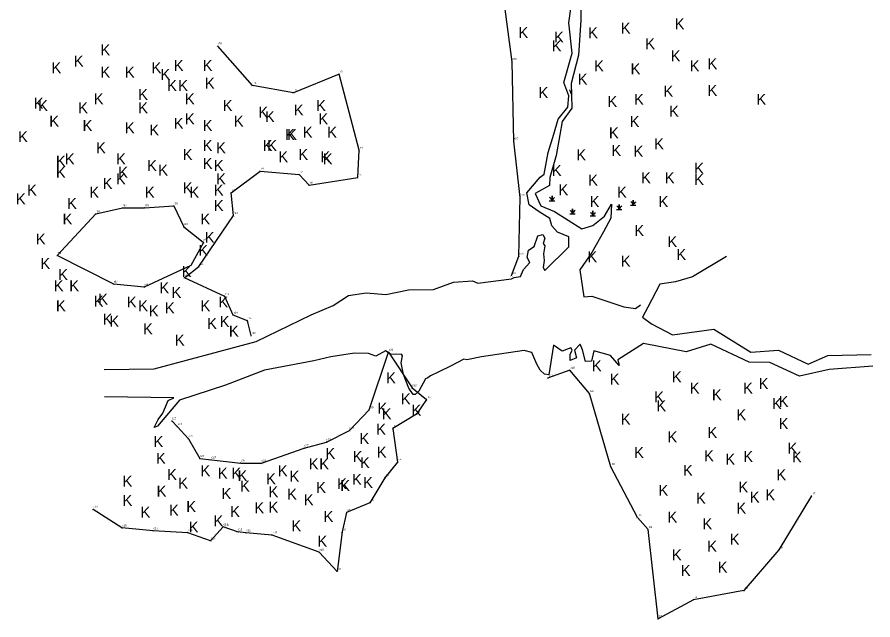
# Model space of a CAD drawing. Extents: x 2028512 to 2029541, y 737100 to 738747.
# Drawn here: x 2028512 to 2029176, y 737100 to 737568 of the extents above; entities that cross this region are included whole.
import ezdxf

# ---------------------------------------------------------------- set-up
doc = ezdxf.new("R2010")
doc.units = 0
for name, color, linetype in [('Exist Hydro Jurisdictional Stream or Body of Water NEU Mitigable', 7, 'Continuous'), ('Exist Hydro Jurisdictional Stream or Body of Water NEU NonMitigable', 7, 'Continuous'), ('Exist Hydro Swamp or Marsh', 7, 'Continuous'), ('Old_Level_10', 7, 'Continuous'), ('Old_Level_20', 7, 'Continuous'), ('Old_Level_52', 7, 'Continuous'), ('Old_Level_55', 7, 'Continuous'), ('Old_Level_61', 7, 'Continuous')]:
    doc.layers.add(name, color=color, linetype=linetype)

msp = doc.modelspace()

# ---------------------------------------------------------------- linework, layer by layer
at = {"layer": 'Exist Hydro Jurisdictional Stream or Body of Water NEU Mitigable'}
for points in [[(2028936, 737517.23), (2028942.42, 737539.85), (2028939.91, 737563.38), (2028944.05, 737593.1), (2028942.37, 737627.04), (2028952.81, 737663.43), (2028963.03, 737695.43), (2028966.79, 737709.62), (2028967.55, 737730.9), (2028965.32, 737734.83), (2028966.1, 737772.62), (2028976.38, 737791.55), (2028994.69, 737794.94), (2029012.11, 737812.51), (2029020.64, 737839.95), (2029044.47, 737843.01), (2029064.89, 737861), (2029074.27, 737865.65)], [(2029086.17, 737861.26), (2029065.82, 737853.05), (2029047.81, 737826.9), (2029032.96, 737828.41), (2029014.3, 737805.56), (2029001.47, 737787.92), (2029013.48, 737774.19), (2029008.57, 737742.32), (2028993.96, 737712.46), (2028973.16, 737694.62), (2028970.92, 737694.24), (2028956.66, 737656.32), (2028948.19, 737625.98), (2028949.49, 737593.57), (2028949.29, 737565.55), (2028947.28, 737538.25), (2028941.59, 737516.37), (2028941.83, 737507.52)], [(2028579.28, 737294.49), (2028618.11, 737294.82), (2028668.37, 737308.4), (2028697.25, 737316.02), (2028739.8, 737336.89), (2028756.85, 737344.17), (2028768.94, 737351.84), (2028782.65, 737353.85), (2028797.96, 737352.7), (2028815.53, 737356.13), (2028834.91, 737356.47), (2028850.48, 737362.29), (2028865.05, 737363.12), (2028869.24, 737361.53), (2028895.29, 737364.79), (2028897.35, 737365.88), (2028902.23, 737366.59), (2028904.64, 737371.95), (2028909.52, 737377.53), (2028907.4, 737381.33), (2028908.6, 737387.08), (2028912.94, 737389.99), (2028915.87, 737398.06), (2028919.61, 737399.24), (2028921.19, 737396.31), (2028919.98, 737392.28), (2028921.28, 737390.26), (2028920.09, 737384.28), (2028920.77, 737379.09), (2028919.88, 737373.45), (2028921.21, 737371.27), (2028939.9, 737389.63), (2028939.73, 737397.45), (2028931.07, 737401.07), (2028926.71, 737405.79), (2028925.13, 737411.52), (2028916.94, 737416.7), (2028909.17, 737422.08), (2028907.26, 737431.54), (2028917.65, 737443.63), (2028920.61, 737446.09), (2028923.86, 737462.71), (2028928.34, 737476.94), (2028931.47, 737488.65), (2028939.13, 737497.99), (2028939.73, 737506.91), (2028936, 737517.23)], [(2028956.69, 737515.78), (2028956.69, 737515.78), (2028956.69, 737515.78)], [(2028940.27, 737511.64), (2028941.83, 737507.52), (2028942.13, 737497.36), (2028934.67, 737486.92), (2028932.85, 737476.66), (2028929.99, 737460.54), (2028925.08, 737443.5), (2028924.85, 737437.17), (2028913.73, 737430.92), (2028918.01, 737421.53), (2028928.81, 737417.07), (2028949.92, 737403.52), (2028958.51, 737406.06), (2028967.65, 737413.3), (2028972.86, 737422.71), (2028972.54, 737411.9), (2028966.68, 737401.35)], [(2028966.68, 737401.35), (2028957.77, 737385.32), (2028948.3, 737371.74), (2028951.59, 737350.67), (2028951.59, 737350.67), (2028957.63, 737351.39), (2028982.64, 737343.14), (2028991.65, 737341.83), (2028995.35, 737344.57)], [(2028997.07, 737335.1), (2029004.09, 737329.88), (2029020.36, 737321.25), (2029052.42, 737325.7), (2029080.99, 737307.79), (2029102.51, 737309.37), (2029125.49, 737298.64), (2029140.85, 737305.29), (2029174.35, 737306.1)], [(2029175.81, 737296.95), (2029141.96, 737294.49), (2029118.74, 737289.3), (2029095.9, 737299.77), (2029079.76, 737299.97), (2029050.15, 737314), (2029030.96, 737308.01), (2028997.7, 737314.69), (2028977.92, 737301.97), (2028978.95, 737297.5), (2028972.13, 737305.22), (2028959.18, 737308.95), (2028957.35, 737300.91), (2028952.91, 737300.7), (2028950.53, 737309.54), (2028948.58, 737314.03), (2028944.32, 737309.45), (2028945.88, 737303.52), (2028940.97, 737301.5), (2028940.99, 737305.95), (2028942.42, 737309.49), (2028941.29, 737311.1), (2028934.72, 737308.65), (2028928, 737313.22), (2028924.46, 737290.33), (2028920.89, 737290.83), (2028917.54, 737293.89), (2028914.92, 737298.41), (2028911.07, 737307.65), (2028905.11, 737309.14), (2028871.99, 737304.25), (2028860.77, 737301.82), (2028858.36, 737302.4), (2028847.98, 737296.86), (2028839.03, 737292.52), (2028832.58, 737289.46), (2028830.34, 737287.86), (2028828.6, 737287.08), (2028823.58, 737277.67), (2028820.68, 737275.02), (2028819.16, 737274.91), (2028815.73, 737279.86), (2028811.67, 737290.39), (2028809.82, 737299.53), (2028810.76, 737305.1), (2028810.06, 737306.41), (2028801.97, 737306.06), (2028797.58, 737308.87), (2028790.08, 737304.86), (2028784.27, 737306.84), (2028773.47, 737307.03), (2028755.08, 737304.25), (2028741.96, 737301.19), (2028703.61, 737293.82), (2028703.61, 737293.82), (2028673.41, 737282.3), (2028637.63, 737270.65), (2028620.59, 737250.44), (2028618.02, 737249.4), (2028621.23, 737255.67), (2028624.74, 737260.61), (2028628.88, 737270.21), (2028633.29, 737272.32), (2028579.58, 737273.18)]]:
    msp.add_lwpolyline(points, dxfattribs=at)
at = {"layer": 'Exist Hydro Jurisdictional Stream or Body of Water NEU NonMitigable'}
msp.add_lwpolyline([(2029062.34, 737382.21), (2029035.93, 737366.44), (2029022.72, 737362.46), (2029010.52, 737360.74), (2029001.14, 737342.82), (2028997.07, 737335.1)], dxfattribs=at)
at = {"layer": 'Exist Hydro Swamp or Marsh'}
for p, q in [((2028926.82, 737427.1), (2028926.82, 737427.1)), ((2028978.92, 737420.34), (2028978.92, 737420.34)), ((2028989.77, 737423.61), (2028989.77, 737423.61)), ((2028942.69, 737416.96), (2028942.69, 737416.96)), ((2028958.45, 737415.32), (2028958.45, 737415.32))]:
    msp.add_line(p, q, dxfattribs=at)
for points in [[(2028924.67, 737425.31), (2028926.83, 737425.31), (2028926.83, 737429.26), (2028926.83, 737425.31), (2028928.98, 737425.31)], [(2028976.77, 737418.55), (2028978.93, 737418.55), (2028978.93, 737422.5), (2028978.93, 737418.55), (2028981.08, 737418.55)], [(2028987.62, 737421.83), (2028989.78, 737421.83), (2028989.78, 737425.78), (2028989.78, 737421.83), (2028991.93, 737421.83)], [(2028940.54, 737415.17), (2028942.69, 737415.17), (2028942.69, 737419.12), (2028942.69, 737415.17), (2028944.84, 737415.17)], [(2028956.3, 737413.54), (2028958.45, 737413.54), (2028958.45, 737417.48), (2028958.45, 737413.54), (2028960.6, 737413.54)]]:
    msp.add_lwpolyline(points, dxfattribs=at)
for centre, radius, start, end in [((2028923.76, 737425.09), 3.07, 4.14034, 67.53497), ((2028931.39, 737423.8), 4.81, 122.12745, 161.62219), ((2028975.86, 737418.33), 3.07, 4.14034, 67.53497), ((2028983.49, 737417.04), 4.81, 122.12745, 161.62219), ((2028986.71, 737421.61), 3.07, 4.14034, 67.53497), ((2028994.34, 737420.32), 4.81, 122.12745, 161.62219), ((2028939.62, 737414.95), 3.07, 4.14034, 67.53497), ((2028947.25, 737413.66), 4.81, 122.12745, 161.62219), ((2028955.39, 737413.31), 3.07, 4.14034, 67.53497), ((2028963.01, 737412.02), 4.81, 122.12745, 161.62219)]:
    msp.add_arc(centre, radius, start, end, dxfattribs=at)
at = {"layer": 'Old_Level_52'}
for points in [[(2028895.42, 737367.29), (2028901.12, 737382.42), (2028902.03, 737427.96), (2028897.22, 737471.61), (2028895.79, 737533.3), (2028886.82, 737601.44), (2028880.64, 737719.02)], [(2028694.5, 737514.77), (2028667.38, 737545.48)], [(2028693.4, 737320.71), (2028690.55, 737332.26), (2028679.49, 737336.57), (2028672.9, 737351.1), (2028641.49, 737365.44), (2028652.64, 737374.31), (2028679.69, 737413.85), (2028677.78, 737431.5), (2028700.22, 737448.42), (2028730.65, 737445.78), (2028738.36, 737437.46), (2028776.16, 737443.51), (2028777.17, 737464.61), (2028761.51, 737523.75), (2028726.26, 737509.21), (2028694.5, 737514.77)], [(2028646.52, 737375.03), (2028610.39, 737358.35), (2028586.64, 737360.64), (2028542.87, 737382.85), (2028572.83, 737415.22), (2028593.56, 737419.88), (2028610.55, 737419.9), (2028633.35, 737421.42), (2028641.02, 737405.22), (2028656.21, 737393.15), (2028656.33, 737393.09), (2028646.52, 737375.03)], [(2028631.79, 737254.52), (2028636.15, 737250), (2028644.82, 737240.66), (2028653.53, 737225.35), (2028662.6, 737224.3), (2028685.23, 737221.76), (2028701.36, 737221.65), (2028734.42, 737233.45), (2028751.76, 737238.1), (2028769.64, 737247.12), (2028784.82, 737262.97), (2028799.89, 737307.85), (2028818.26, 737280.17), (2028829.48, 737271.13), (2028821.53, 737259.75), (2028803.29, 737248.65), (2028807, 737222.55), (2028797.08, 737210.34), (2028785.33, 737191.01), (2028767.41, 737183.39), (2028763.87, 737168.27), (2028759.99, 737137.67), (2028746.04, 737152.6), (2028709.71, 737165.9), (2028689.31, 737167.63), (2028682.75, 737168.31), (2028671.67, 737172.24), (2028661.89, 737161.44), (2028644.29, 737167.68), (2028617.36, 737169.18), (2028593.06, 737171.4), (2028570.75, 737185.76), (2028570.79, 737185.85)]]:
    msp.add_lwpolyline(points, dxfattribs=at)
at = {"layer": 'Old_Level_55'}
msp.add_lwpolyline([(2029128.06, 737196.31), (2029102.78, 737154.4), (2029075.75, 737122.77), (2029036.51, 737115.67), (2029009.19, 737100.79), (2029001.45, 737170.2), (2028993.06, 737179.45), (2028972.4, 737218.95), (2028955.96, 737275.67), (2028940.73, 737293.83), (2028923.43, 737287.61)], dxfattribs=at)

# ---------------------------------------------------------------- texts
at = {"layer": 'Old_Level_10'}
for p in [(2029022, 737558.4), (2028900.79, 737551.66), (2028954.83, 737551.56), (2028980.17, 737555.11), (2028928.4, 737548.21), (2028576.36, 737538.19), (2028926.67, 737541.3), (2028999.15, 737543.03), (2029018.89, 737533.53), (2028538.39, 737524.38), (2028555.65, 737529.56), (2028616.05, 737524.38), (2028633.3, 737526.11), (2028655.74, 737526.11), (2028959.46, 737525.76), (2029033.67, 737525.76), (2029047.47, 737527.49), (2028576.36, 737520.93), (2028595.34, 737520.93), (2028622.95, 737519.2), (2028987.8, 737523.57), (2028657.46, 737512.3), (2028946.75, 737515.49), (2028628.13, 737510.57), (2028636.76, 737510.57), (2028916.32, 737505.04), (2029013.3, 737506.16), (2029047.47, 737506.77), (2028571.18, 737500.21), (2028605.69, 737503.66), (2028641.93, 737500.21), (2028969.82, 737498.14), (2028990.52, 737499.86), (2029085.44, 737499.86), (2028524.59, 737496.76), (2028528.04, 737495.03), (2028559.1, 737493.3), (2028605.69, 737493.3), (2028671.27, 737495.03), (2028726.49, 737491.58), (2028743.75, 737495.03), (2028641.93, 737484.67), (2028698.88, 737489.85), (2028704.06, 737486.4), (2028745.48, 737484.67), (2029017.65, 737490.61), (2028536.67, 737482.94), (2028562.55, 737479.49), (2028595.34, 737477.76), (2028633.3, 737481.22), (2028655.74, 737479.49), (2028679.9, 737482.94), (2028987.07, 737482.6), (2028614.32, 737476.04), (2028719.59, 737472.58), (2028721.32, 737472.58), (2028733.4, 737474.31), (2028752.38, 737474.31), (2028971, 737473.82), (2028971, 737473.82), (2028512.51, 737470.86), (2029006.05, 737465.33), (2028572.91, 737462.22), (2028655.74, 737463.95), (2028666.09, 737462.22), (2028702.33, 737463.95), (2028705.78, 737463.95), (2028972.87, 737460.14), (2028990.05, 737459.52), (2028541.84, 737451.86), (2028548.75, 737453.59), (2028588.44, 737453.59), (2028640.21, 737457.04), (2028714.41, 737455.32), (2028729.94, 737457.04), (2028747.2, 737455.32), (2028748.93, 737453.59), (2028945.66, 737456.7), (2028612.6, 737448.41), (2028621.23, 737444.96), (2028655.74, 737450.14), (2028664.37, 737448.41), (2028926.67, 737444.61), (2029037.12, 737446.34), (2028541.84, 737443.23), (2028588.44, 737438.05), (2028590.16, 737443.23), (2028666.09, 737438.05), (2028995.88, 737438.99), (2029014.3, 737438.99), (2029037.12, 737437.71), (2028578.08, 737434.6), (2028640.21, 737431.14), (2028954.83, 737437.13), (2028519.41, 737429.42), (2028567.73, 737427.69), (2028610.87, 737427.69), (2028645.39, 737427.69), (2028664.37, 737429.42), (2028931.82, 737429.66), (2028977.22, 737427.8), (2028510.78, 737422.51), (2028550.47, 737419.06), (2028956.01, 737420.44), (2029009.51, 737420.44), (2028664.37, 737417.33), (2028547.02, 737406.97), (2028654.01, 737406.97), (2028990.67, 737397.94), (2028526.31, 737391.43), (2028657.4, 737392.73), (2029016.41, 737389.36), (2028652.36, 737382.64), (2029023.31, 737379.35), (2028529.76, 737372.44), (2028954.28, 737377.62), (2028980.17, 737374.17), (2028639.4, 737366.31), (2028543.57, 737363.81), (2028540.12, 737355.17), (2028552.2, 737355.17), (2028622.12, 737353.59), (2028574.63, 737344.81), (2028631.58, 737349.99), (2028541.84, 737339.64), (2028571.18, 737343.09), (2028596.92, 737342.54), (2028605.69, 737339.64), (2028654.01, 737339.64), (2028667.96, 737342.54), (2028613.96, 737335.58), (2028626.4, 737337.91), (2028578.08, 737329.28), (2028583.26, 737327.55), (2028659.19, 737325.82), (2028668.92, 737327.42), (2028609.4, 737321.66), (2028676.11, 737319.97), (2028634.12, 737313.01), (2028957.74, 737293.02), (2028798.02, 737283.62), (2028971.54, 737282.66), (2029019.86, 737284.38), (2029087.16, 737279.2), (2029033.67, 737275.75), (2029075.08, 737275.75), (2028809.54, 737267.3), (2029006.05, 737268.84), (2029050.92, 737270.57), (2029102.69, 737265.39), (2028791.3, 737260.09), (2028817.7, 737258.65), (2029007.78, 737261.94), (2029097.52, 737263.66), (2028794.66, 737255.77), (2029069.91, 737255.03), (2028980.17, 737251.58), (2029102.69, 737248.13), (2028790.34, 737243.77), (2029047.47, 737241.22), (2028617.56, 737234.16), (2028777.38, 737236.56), (2029016.41, 737237.77), (2028790.82, 737226), (2028990.52, 737225.68), (2029109.6, 737229.13), (2028619.48, 737221.2), (2028750.99, 737225.04), (2028772.1, 737222.64), (2029044.78, 737223.18), (2029061.28, 737220.5), (2029075.25, 737222.56), (2029113.05, 737222.23), (2028738.03, 737216.87), (2028746.19, 737216.87), (2028777.86, 737217.83), (2028628.12, 737208.71), (2028654.04, 737211.59), (2028667.48, 737209.67), (2028678.03, 737209.67), (2028682.83, 737207.75), (2028704.91, 737205.35), (2028714.03, 737211.59), (2028723.15, 737207.27), (2029028.49, 737211.87), (2029100.97, 737208.41), (2028593.56, 737203.43), (2028636.76, 737201.99), (2028684.75, 737199.59), (2028743.79, 737198.63), (2028760.11, 737201.51), (2028762.51, 737200.07), (2028771.63, 737204.87), (2028780.26, 737202.47), (2029071.52, 737198.93), (2028619.96, 737195.75), (2028670.36, 737193.82), (2028706.83, 737195.27), (2028721.23, 737193.34), (2029009.51, 737196.33), (2029092.34, 737192.87), (2028593.56, 737188.54), (2028734.19, 737189.02), (2029038.56, 737190.22), (2029080.26, 737191.15), (2028607.48, 737179.42), (2028629.56, 737180.86), (2028643, 737183.74), (2028677.07, 737179.9), (2028695.79, 737182.78), (2028706.83, 737183.26), (2029069.91, 737182.51), (2028664.12, 737172.7), (2028749.55, 737176.06), (2029016.41, 737175.61), (2028644.92, 737167.89), (2028724.59, 737168.85), (2029043.53, 737170.32), (2028744.75, 737156.85), (2029047.26, 737152.9), (2029064.73, 737158.34), (2029019.86, 737146.26), (2029026.76, 737134.17), (2029055.35, 737136.73)]:
    msp.add_text('K', height=8.5, dxfattribs=at).set_placement(p)
at = {"layer": 'Old_Level_20'}
for p in [(2028666.63, 737544.73), (2028895.04, 737532.55), (2028760.76, 737523), (2028693.75, 737514.02), (2028725.51, 737508.46), (2028896.47, 737470.86), (2028776.42, 737463.86), (2028699.47, 737447.67), (2028729.9, 737445.03), (2028775.41, 737442.76), (2028737.61, 737436.71), (2028677.03, 737430.75), (2028901.28, 737427.21), (2028592.81, 737419.13), (2028609.8, 737419.15), (2028632.6, 737420.67), (2028572.08, 737414.47), (2028678.94, 737413.1), (2028640.27, 737404.47), (2028655.58, 737392.34), (2028542.12, 737382.1), (2028900.37, 737381.67), (2028651.89, 737373.56), (2028894.67, 737366.54), (2028585.89, 737359.89), (2028640.74, 737364.69), (2028609.64, 737357.6), (2028672.15, 737350.35), (2028678.74, 737335.82), (2028689.8, 737331.51), (2028692.65, 737319.96), (2028799.14, 737307.1), (2028939.98, 737293.08), (2028922.68, 737286.86), (2028817.51, 737279.42), (2028955.21, 737274.92), (2028828.73, 737270.38), (2028784.07, 737262.22), (2028820.78, 737259), (2028631.04, 737253.77), (2028635.4, 737249.25), (2028768.89, 737246.37), (2028802.54, 737247.9), (2028644.07, 737239.91), (2028733.67, 737232.7), (2028751.01, 737237.35), (2028652.78, 737224.6), (2028661.85, 737223.55), (2028684.48, 737221.01), (2028700.61, 737220.9), (2028806.25, 737221.8), (2028971.65, 737218.2), (2028796.33, 737209.59), (2029127.31, 737195.56), (2028784.58, 737190.26), (2028570.04, 737185.1), (2028766.66, 737182.64), (2028992.31, 737178.7), (2028592.31, 737170.65), (2028616.61, 737168.43), (2028643.54, 737166.93), (2028670.92, 737171.49), (2028672.54, 737171.01), (2028682, 737167.56), (2028688.56, 737166.88), (2028763.12, 737167.52), (2029000.7, 737169.45), (2028661.14, 737160.69), (2028708.96, 737165.15), (2029102.03, 737153.65), (2028745.29, 737151.85), (2028759.24, 737136.92), (2029075, 737122.02), (2029035.76, 737114.92), (2029008.44, 737100.04)]:
    msp.add_text('A', height=1.5, dxfattribs=at).set_placement(p)
at = {"layer": 'Old_Level_61'}
for s, p in [('r70', (2028667.49, 737546.73)), ('a78', (2028895.84, 737534.55)), ('r3', (2028762.36, 737525)), ('r1', (2028695.6, 737516.02)), ('r2', (2028727.11, 737510.46)), ('a77', (2028897.26, 737472.86)), ('r4', (2028778.02, 737465.86)), ('r8', (2028701.07, 737449.67)), ('r7', (2028731.5, 737447.03)), ('r5', (2028777.01, 737444.76)), ('r6', (2028739.21, 737438.71)), ('r9', (2028678.62, 737432.75)), ('a76', (2028902.08, 737429.21)), ('r90', (2028593.68, 737421.13)), ('r91', (2028610.92, 737421.15)), ('r92', (2028633.47, 737422.67)), ('r99', (2028572.95, 737416.47)), ('r10', (2028680.05, 737415.1)), ('r93', (2028641.13, 737406.47)), ('r94', (2028656.45, 737394.34)), ('r98', (2028542.98, 737384.1)), ('a75', (2028901.17, 737383.67)), ('r11', (2028653.26, 737375.56)), ('r12', (2028641.85, 737366.69)), ('a74', (2028895.47, 737368.54)), ('r97', (2028586.75, 737361.89)), ('r96', (2028610.5, 737359.6)), ('r13', (2028673.26, 737352.35)), ('r14', (2028679.86, 737337.82)), ('r15', (2028690.92, 737333.51)), ('r16', (2028693.76, 737321.96)), ('c31', (2028800.22, 737309.1)), ('b10', (2028941.02, 737295.08)), ('b11', (2028923.97, 737288.86)), ('c32', (2028818.33, 737281.42)), ('c1', (2028830.51, 737272.38)), ('b9', (2028956.73, 737276.92)), ('c30', (2028784.89, 737264.22)), ('c2', (2028822.31, 737261)), ('c20', (2028631.83, 737255.77)), ('c21', (2028636.45, 737251.25)), ('c29', (2028769.68, 737248.37)), ('c3', (2028804.06, 737249.9)), ('c22', (2028644.87, 737241.91)), ('c28', (2028751.81, 737239.35)), ('c27', (2028734.46, 737234.7)), ('c23', (2028653.58, 737226.6)), ('c24', (2028662.64, 737225.55)), ('c25', (2028685.27, 737223.01)), ('c26', (2028701.4, 737222.9)), ('c4', (2028807.78, 737223.8)), ('b8', (2028973.18, 737220.2)), ('c5', (2028797.86, 737211.59)), ('b7', (2029128.84, 737197.56)), ('c19', (2028571.09, 737187.1)), ('c6', (2028786.11, 737192.26)), ('c7', (2028768.18, 737184.64)), ('b1', (2028994.09, 737180.7)), ('c18', (2028593.35, 737172.65)), ('c14', (2028671.96, 737173.49)), ('e', (2028674.8, 737173.01)), ('c17', (2028617.65, 737170.43)), ('c16', (2028644.58, 737168.93)), ('c13', (2028683.04, 737169.56)), ('c12', (2028689.6, 737168.88)), ('c11', (2028710.26, 737167.15)), ('c8', (2028764.65, 737169.52)), ('b2', (2029002.23, 737171.45)), ('c15', (2028662.18, 737162.69)), ('c10', (2028746.33, 737153.85)), ('b6', (2029103.55, 737155.65)), ('c9', (2028760.77, 737138.92)), ('b5', (2029076.53, 737124.02)), ('b4', (2029037.29, 737116.92)), ('b3', (2029009.97, 737102.04))]:
    msp.add_text(s, height=1.5, dxfattribs=at).set_placement(p)

doc.saveas('drawing.dxf')
